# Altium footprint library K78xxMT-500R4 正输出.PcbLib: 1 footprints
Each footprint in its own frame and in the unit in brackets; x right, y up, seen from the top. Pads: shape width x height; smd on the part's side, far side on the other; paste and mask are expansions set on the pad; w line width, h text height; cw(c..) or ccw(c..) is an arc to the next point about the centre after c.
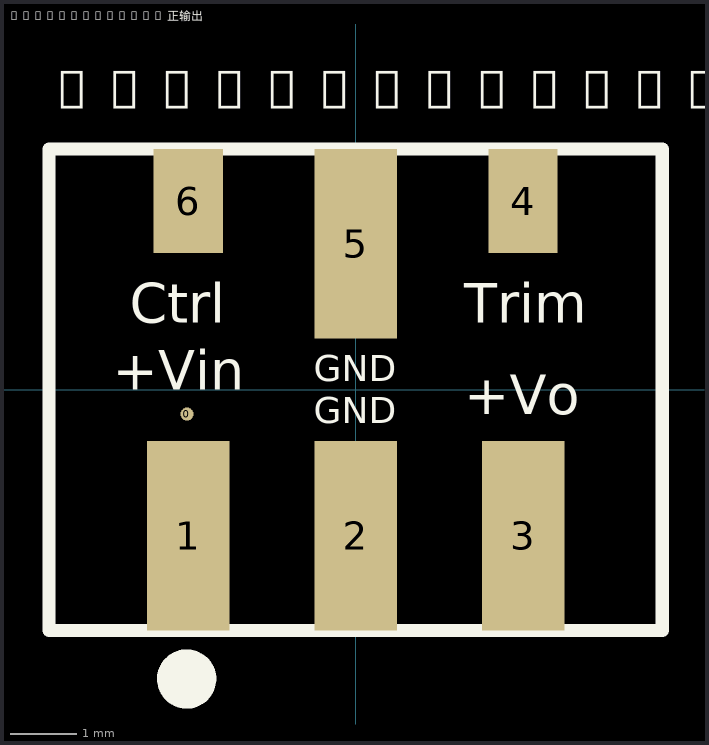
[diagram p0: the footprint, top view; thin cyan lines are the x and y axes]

## K78xxMT-500R4 正输出 [mm]
pads (7):
  round 0.2 smd mask+0.1: 0(-2.557,-0.369)
  rect 1.25x2.87 smd mask+0.102: 1(-2.54,-2.215) 2(0,-2.215) 3(2.54,-2.215) 5(0,2.215)
  rect 1.05x1.58 smd mask+0.102: 4(2.54,2.86) 6(-2.54,2.86)
Top Overlay:
  lines w0.2: -4.65,-3.65 -4.65,3.65 4.65,3.65 4.65,-3.65 -4.65,-3.65
  lines w0.5: -2.373,-4.45 cw(c-2.562,-4.387) -2.364,-4.412
  text "Ctrl" at -3.429,1.016 h0.6
  text "Trim" at 1.651,1.016 h0.6
  text "+Vo" at 1.651,-0.369 h0.6
  text "GND" at -0.635,-0.508 h0.4
  text "+Vin" at -3.683,0 h0.6
  text "K78xxMT-500R4 正输出" at -4.699,4.064 h1
  text "GND" at -0.635,0.127 h0.4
